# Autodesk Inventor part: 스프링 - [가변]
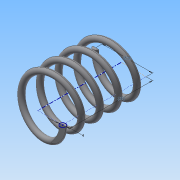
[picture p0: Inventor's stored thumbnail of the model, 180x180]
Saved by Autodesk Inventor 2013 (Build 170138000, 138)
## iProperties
Created: 2015-03
Part Number: 스프링 - [가변]
Material: 강철, 탄소
Document SubType Name: Modeling
Designer: Administrator
Density: 7.87 g/cm^3
Mass: 47.9648 g
Surface Area: 62.0176 cm^2
Volume: 6.09464 cm^3
Author: Administrator
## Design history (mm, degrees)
sketch "스케치1"
  geometry: L1 (0, 0)-(17.5, 0); L2 (17.5, 0)-(17.5, 43.5); L3 (17.5, 43.5)-(0, 43.5); L4 (0, 43.5)-(0, 0); C1 r 2 at (17.5, 0)
  constraints: 8 end point, 2 parallel, 1 centre point, 1 coincident, 1 horizontal, 1 perpendicular
  dimensions: "d0" = 4 diameter of C1; "d2" = 35 diameter of L2 L4; "d3" = 43.5 distance of L1.end L2.end (derived)
feature "코일1" sketch "스케치1" pitch "d4" = 10; turns "d6" = 4.5; dims "d5" = 43.5 (= d3), "d7" = 0, angle "d8" = 90 deg, angle "d9" = 90 deg, "d10" = 0, "d11" = 0
sketch "스케치2"
  geometry: L1 (-19.5, 0)-(-15.5, 0) reference; 1 further point
  constraints: 1 horizontal alignment
extrude "돌출1" cut sketch "스케치2" distance "d12" = 10; taper "d13" = 0 deg
node "작업 평면1"
sketch "스케치3"
  geometry: L1 (15.5, 0)-(19.5, 0) reference; 1 further point
  constraints: 1 horizontal alignment
extrude "돌출2" cut sketch "스케치3" distance "d15" = 10; taper "d16" = 0 deg
node "솔리드1"
node "절단 모서리 투영1"
node "절단 모서리 투영2"
other parameters: "d14" = 43.5 (= d3)
